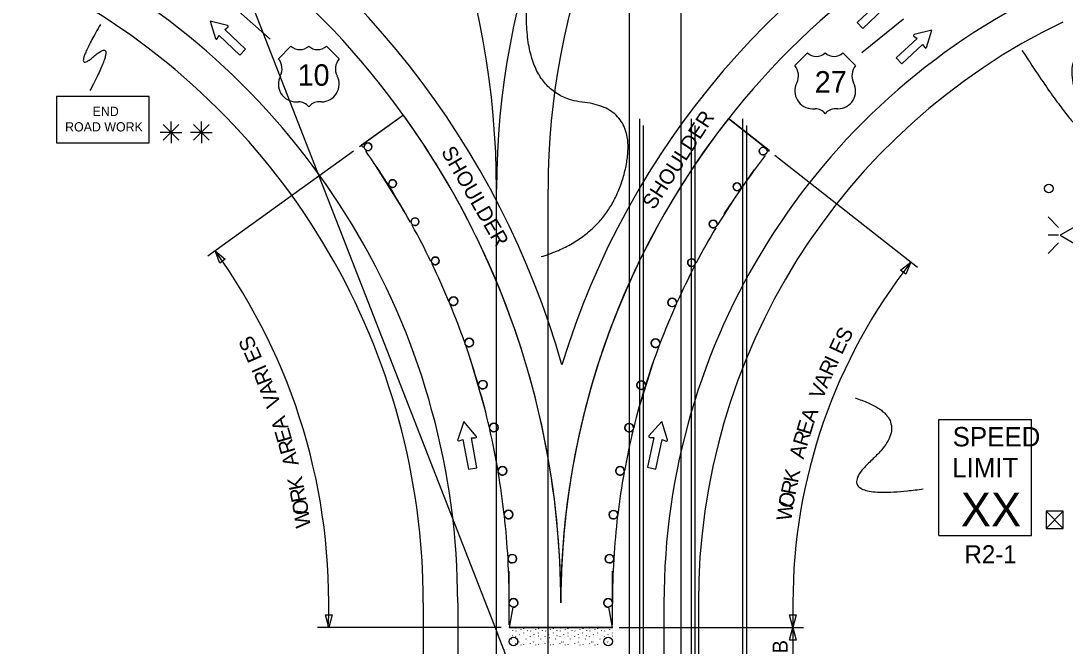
# Model space of a CAD drawing. Extents: x 16604 to 19504, y 6997 to 8305.
# Drawn here: x 16712.4 to 17198.4, y 7731.2 to 8022 of the extents above; entities that cross this region are included whole.
import ezdxf

# ---------------------------------------------------------------- set-up
doc = ezdxf.new("R2010")
doc.units = 0
for name, color, linetype in [('ALI_LEGAL_EX', 7, 'Continuous'), ('MT_SCRATCH_LEVEL_A', 7, 'Continuous'), ('MT_SCRATCH_LEVEL_E', 7, 'Continuous'), ('PAVT_EDGE_EX', 7, 'Continuous'), ('TRAFFIC_SIGNS_PR', 7, 'Continuous'), ('TYPICAL_EX', 7, 'Continuous'), ('TYPICAL_TEXT_DIMEN_PR', 7, 'Continuous')]:
    doc.layers.add(name, color=color, linetype=linetype)

msp = doc.modelspace()

# ---------------------------------------------------------------- linework, layer by layer
at = {"layer": 'ALI_LEGAL_EX'}
for p, q in [((16712.44, 8305.01), (16934.47, 7736.64)), ((16995.53, 8241.3), (16995.53, 7423.16)), ((17019.53, 8241.3), (17019.53, 7423.16)), ((17000.51, 7366.28), (17000.51, 7976.48)), ((17024.51, 7366.28), (17024.51, 7976.48)), ((17048.51, 7366.28), (17048.51, 7976.48)), ((17002.26, 7363.06), (17002.26, 7973.25)), ((17026.26, 7363.06), (17026.26, 7973.25)), ((17050.26, 7363.06), (17050.26, 7973.25)), ((16933.79, 7333.59), (16933.79, 7943.78)), ((16933.79, 7333.59), (16933.79, 7943.78)), ((16957.79, 7333.59), (16957.79, 7943.78))]:
    msp.add_line(p, q, dxfattribs=at)
for points in [[(16828.4, 8013.47), (16809.73, 8030.1)], [(17103.8, 8007.23), (17123.26, 8022.93)], [(16890.91, 7933.35), (16877.68, 7954.57)], [(17039.8, 7932.22), (17053.92, 7952.85)], [(16928.64, 7840.65), (16921.64, 7864.65)], [(16999.66, 7840.57), (17007.11, 7864.44)], [(16939.73, 7741.09), (16939.73, 7766.09)], [(16987.73, 7741.09), (16987.73, 7766.09)]]:
    msp.add_lwpolyline(points, dxfattribs=at)
for centre, radius, start, end in [((16545.79, 7943.78), 388, 0, 40.1908), ((17297.79, 7943.78), 364, 137.516, 180), ((17297.79, 7943.78), 340, 137.516, 180), ((16595.41, 7604.2), 364, 341.1459, 21.3367)]:
    msp.add_arc(centre, radius, start, end, dxfattribs=at)
at = {"layer": 'MT_SCRATCH_LEVEL_A'}
for p, q in [((16987.73, 7739.84), (16939.73, 7739.84)), ((16939.73, 7739.84), (16987.73, 7739.84)), ((16987.73, 7739.84), (16939.73, 7739.84)), ((16941.23, 7738.38), (16941.28, 7738.3)), ((16942.68, 7739.5), (16942.73, 7739.62)), ((16942.76, 7738.24), (16942.81, 7738.16)), ((16945.05, 7739.05), (16945.1, 7738.98)), ((16946.32, 7737.32), (16946.38, 7737.24)), ((16946.49, 7739.2), (16946.55, 7739.32)), ((16948.11, 7738.38), (16948.17, 7738.3)), ((16949.56, 7739.5), (16949.62, 7739.62)), ((16949.64, 7738.24), (16949.69, 7738.16)), ((16951.93, 7739.05), (16951.99, 7738.98)), ((16953.21, 7737.32), (16953.26, 7737.24)), ((16953.38, 7739.2), (16953.43, 7739.32)), ((16955, 7738.38), (16955.05, 7738.3)), ((16956.45, 7739.5), (16956.5, 7739.62)), ((16956.53, 7738.24), (16956.58, 7738.16)), ((16958.82, 7739.05), (16958.87, 7738.98)), ((16960.1, 7737.32), (16960.15, 7737.24)), ((16960.27, 7739.2), (16960.32, 7739.32)), ((16961.89, 7738.38), (16961.94, 7738.3)), ((16963.34, 7739.5), (16963.39, 7739.62)), ((16963.42, 7738.24), (16963.47, 7738.16)), ((16965.71, 7739.05), (16965.76, 7738.98)), ((16966.99, 7737.32), (16967.04, 7737.24)), ((16967.16, 7739.2), (16967.21, 7739.32)), ((16968.78, 7738.38), (16968.83, 7738.3)), ((16970.23, 7739.5), (16970.28, 7739.62)), ((16970.31, 7738.24), (16970.36, 7738.16)), ((16972.6, 7739.05), (16972.65, 7738.98)), ((16973.87, 7737.32), (16973.92, 7737.24)), ((16974.05, 7739.2), (16974.1, 7739.32)), ((16975.66, 7738.38), (16975.72, 7738.3)), ((16977.11, 7739.5), (16977.17, 7739.62)), ((16977.19, 7738.24), (16977.24, 7738.16)), ((16979.48, 7739.05), (16979.53, 7738.98)), ((16980.76, 7737.32), (16980.81, 7737.24)), ((16980.93, 7739.2), (16980.98, 7739.32)), ((16982.55, 7738.38), (16982.6, 7738.3)), ((16984, 7739.5), (16984.05, 7739.62)), ((16984.08, 7738.24), (16984.13, 7738.16)), ((16986.37, 7739.05), (16986.42, 7738.98)), ((16987.65, 7737.32), (16987.7, 7737.24)), ((16940.66, 7734.41), (16940.71, 7734.53)), ((16941.28, 7736.17), (16941.33, 7736.09)), ((16942.56, 7735.59), (16942.57, 7735.47)), ((16942.68, 7732.22), (16942.73, 7732.33)), ((16943.44, 7733.18), (16943.49, 7733.1)), ((16944.18, 7733.15), (16944.23, 7733.07)), ((16944.4, 7736.45), (16944.45, 7736.56)), ((16944.59, 7735.25), (16944.64, 7735.17)), ((16946.37, 7735.92), (16946.42, 7736.03)), ((16946.49, 7731.92), (16946.55, 7732.04)), ((16947.54, 7734.41), (16947.6, 7734.53)), ((16948.16, 7736.17), (16948.21, 7736.09)), ((16949.44, 7735.59), (16949.46, 7735.47)), ((16949.56, 7732.22), (16949.62, 7732.33)), ((16950.33, 7733.18), (16950.38, 7733.1)), ((16951.06, 7733.15), (16951.12, 7733.07)), ((16951.28, 7736.45), (16951.34, 7736.56)), ((16951.47, 7735.25), (16951.53, 7735.17)), ((16953.25, 7735.92), (16953.31, 7736.03)), ((16953.38, 7731.92), (16953.43, 7732.04)), ((16954.43, 7734.41), (16954.48, 7734.53)), ((16955.05, 7736.17), (16955.1, 7736.09)), ((16956.33, 7735.59), (16956.34, 7735.47)), ((16956.45, 7732.22), (16956.5, 7732.33)), ((16957.22, 7733.18), (16957.27, 7733.1)), ((16957.95, 7733.15), (16958, 7733.07)), ((16958.17, 7736.45), (16958.22, 7736.56)), ((16958.36, 7735.25), (16958.41, 7735.17)), ((16960.14, 7735.92), (16960.19, 7736.03)), ((16960.27, 7731.92), (16960.32, 7732.04)), ((16961.32, 7734.41), (16961.37, 7734.53)), ((16961.94, 7736.17), (16961.99, 7736.09)), ((16963.22, 7735.59), (16963.23, 7735.47)), ((16963.34, 7732.22), (16963.39, 7732.33)), ((16964.1, 7733.18), (16964.15, 7733.1)), ((16964.84, 7733.15), (16964.89, 7733.07)), ((16965.06, 7736.45), (16965.11, 7736.56)), ((16965.25, 7735.25), (16965.3, 7735.17)), ((16967.03, 7735.92), (16967.08, 7736.03)), ((16967.16, 7731.92), (16967.21, 7732.04)), ((16968.21, 7734.41), (16968.26, 7734.53)), ((16968.83, 7736.17), (16968.88, 7736.09)), ((16970.11, 7735.59), (16970.12, 7735.47)), ((16970.23, 7732.22), (16970.28, 7732.33)), ((16970.99, 7733.18), (16971.04, 7733.1)), ((16971.73, 7733.15), (16971.78, 7733.07)), ((16971.95, 7736.45), (16972, 7736.56)), ((16972.14, 7735.25), (16972.19, 7735.17)), ((16973.92, 7735.92), (16973.97, 7736.03)), ((16974.05, 7731.92), (16974.1, 7732.04)), ((16975.09, 7734.41), (16975.15, 7734.53)), ((16975.71, 7736.17), (16975.76, 7736.09)), ((16976.99, 7735.59), (16977.01, 7735.47)), ((16977.11, 7732.22), (16977.17, 7732.33)), ((16977.88, 7733.18), (16977.93, 7733.1)), ((16978.62, 7733.15), (16978.67, 7733.07)), ((16978.83, 7736.45), (16978.89, 7736.56)), ((16979.02, 7735.25), (16979.08, 7735.17)), ((16980.8, 7735.92), (16980.85, 7736.03)), ((16980.93, 7731.92), (16980.98, 7732.04)), ((16981.98, 7734.41), (16982.03, 7734.53)), ((16982.6, 7736.17), (16982.65, 7736.09)), ((16983.88, 7735.59), (16983.89, 7735.47)), ((16984, 7732.22), (16984.05, 7732.33)), ((16984.76, 7733.18), (16984.82, 7733.1)), ((16985.5, 7733.15), (16985.55, 7733.07)), ((16985.72, 7736.45), (16985.78, 7736.56)), ((16985.91, 7735.25), (16985.96, 7735.17)), ((16987.69, 7735.92), (16987.73, 7736)), ((16945.05, 7731.77), (16945.1, 7731.69)), ((16951.93, 7731.77), (16951.99, 7731.69)), ((16958.82, 7731.77), (16958.87, 7731.69)), ((16965.71, 7731.77), (16965.76, 7731.69)), ((16972.6, 7731.77), (16972.65, 7731.69)), ((16979.48, 7731.77), (16979.53, 7731.69)), ((16986.37, 7731.77), (16986.42, 7731.69))]:
    msp.add_line(p, q, dxfattribs=at)
for centre, radius, start, end in [((17327.73, 7751.28), 364, 155.5409, 180), ((17327.73, 7751.28), 364, 155.5409, 180), ((16575.73, 7751.28), 388, 0, 22.8554), ((16575.73, 7751.28), 388, 0, 22.8554)]:
    msp.add_arc(centre, radius, start, end, dxfattribs=at)
at = {"layer": 'MT_SCRATCH_LEVEL_E'}
for p, q in [((17111.32, 8030.27), (17101.65, 8021.2)), ((17104.21, 8018.47), (17113.88, 8027.53)), ((16808.64, 8019.82), (16800.53, 8021.79)), ((16800.53, 8021.79), (16802.96, 8013.82)), ((16807.35, 8017.93), (16808.8, 8019)), ((17101.65, 8021.2), (17104.21, 8018.47)), ((16803.79, 8013.7), (16804.78, 8015.21)), ((16804.78, 8015.21), (16814.4, 8006.1)), ((16816.98, 8008.81), (16807.35, 8017.93)), ((17129.52, 8013.8), (17119.85, 8004.73)), ((17128.08, 8014.88), (17129.52, 8013.8)), ((17136.34, 8017.65), (17128.24, 8015.7)), ((17133.89, 8009.67), (17136.34, 8017.65)), ((17122.41, 8002), (17132.08, 8011.07)), ((17132.08, 8011.07), (17133.06, 8009.55)), ((16814.4, 8006.1), (16816.98, 8008.81)), ((17119.85, 8004.73), (17122.41, 8002))]:
    msp.add_line(p, q, dxfattribs=at)
for centre, start, end in [((16808.52, 8019.37), 306.594, 76.331), ((16803.4, 8013.97), 196.9827, 326.5217), ((17128.36, 8015.24), 103.5821, 233.121), ((17133.45, 8009.82), 213.1934, 342.9303)]:
    msp.add_arc(centre, 0.463, start, end, dxfattribs=at)
at = {"layer": 'PAVT_EDGE_EX'}
for p, q in [((16899.73, 7751.28), (16899.73, 7396.71)), ((16915.73, 7751.28), (16915.73, 7396.71)), ((17011.73, 7751.28), (17011.73, 7396.71)), ((17027.73, 7751.28), (17027.73, 7396.71))]:
    msp.add_line(p, q, dxfattribs=at)
for centre, radius, start, end in [((16575.73, 7751.28), 404, 15.917, 60.4732), ((17327.73, 7751.28), 380, 115.7657, 163.0483), ((16575.73, 7751.28), 388, 0, 60.4732), ((17327.73, 7751.28), 364, 115.7657, 180), ((16575.73, 7751.28), 340, 0, 60.4732), ((17327.73, 7751.28), 316, 115.7657, 180), ((16575.73, 7751.28), 324, 0, 60.4732), ((17327.73, 7751.28), 300, 115.7657, 180), ((17327.73, 7751.28), 300, 180, 180.00000277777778)]:
    msp.add_arc(centre, radius, start, end, dxfattribs=at)
at = {"layer": 'TRAFFIC_SIGNS_PR'}
for p, q in [((17190.48, 7930.78), (17195.41, 7925.84)), ((17195.41, 7922.29), (17190.48, 7922.29)), ((17190.48, 7913.8), (17195.41, 7918.73)), ((17139.59, 7836.6), (17182.79, 7836.6)), ((17139.59, 7782.6), (17139.59, 7836.6)), ((17182.79, 7782.6), (17182.79, 7836.6)), ((17139.59, 7782.6), (17182.79, 7782.6))]:
    msp.add_line(p, q, dxfattribs=at)
msp.add_lwpolyline([(16728.96, 7965.21), (16772.16, 7965.21), (16772.16, 7986.81), (16728.96, 7986.81)], close=True, dxfattribs=at)
msp.add_lwpolyline([(17205.49, 7927.56), (17196.19, 7922.29), (17205.49, 7916.97)], dxfattribs=at)
for centre, radius in [((16873.98, 7963.42), 1.8), ((17057.89, 7961.41), 1.8), ((16885.43, 7946.33), 1.8), ((17045.75, 7944.81), 1.8), ((17190.82, 7943.97), 2), ((16895.89, 7928.63), 1.8), ((17034.63, 7927.51), 1.8), ((16905.35, 7910.36), 1.8), ((17024.57, 7909.57), 1.8), ((16913.77, 7891.6), 2), ((17015.59, 7891.06), 2), ((16921.12, 7872.38), 2), ((17007.76, 7872.05), 2), ((16927.38, 7852.79), 2), ((17001.08, 7852.59), 2), ((16932.52, 7832.88), 2), ((16995.58, 7832.78), 2), ((16936.54, 7812.7), 2), ((16991.28, 7812.66), 2), ((16939.42, 7792.34), 2), ((16988.2, 7792.33), 2), ((16941.15, 7771.84), 2), ((16986.34, 7771.84), 2), ((16941.73, 7751.28), 2), ((16985.72, 7751.28), 2), ((16941.73, 7733.28), 2), ((16985.72, 7733.28), 2)]:
    msp.add_circle(centre, radius, dxfattribs=at)
at = {"layer": 'TYPICAL_EX'}
for p, q in [((16832.26, 8004.38), (16838.15, 8010.27)), ((16860.56, 8004.38), (16854.66, 8010.27)), ((17072.63, 8001.2), (17078.53, 8007.09)), ((17100.93, 8001.2), (17095.03, 8007.09)), ((16840.51, 7984.32), (16841.68, 7984.32)), ((16852.31, 7984.32), (16851.13, 7984.32)), ((17080.88, 7981.14), (17082.05, 7981.14)), ((17092.68, 7981.14), (17091.5, 7981.14))]:
    msp.add_line(p, q, dxfattribs=at)
for centre, radius, start, end in [((16842.28, 8014.57), 5.96, 226.1404, 313.8596), ((16850.54, 8014.57), 5.96, 226.1404, 313.8596), ((16826.67, 7999.66), 7.31, 333.0977, 40.1936), ((16866.14, 7999.66), 7.31, 139.8064, 206.9023), ((17082.65, 8011.38), 5.96, 226.1404, 313.8596), ((17090.91, 8011.38), 5.96, 226.1404, 313.8596), ((17067.04, 7996.47), 7.31, 333.0977, 40.1936), ((17106.51, 7996.47), 7.31, 139.8064, 206.9023), ((16840.52, 7992.56), 8.24, 152.6698, 269.9013), ((16852.3, 7992.56), 8.24, 270.0987, 27.3302), ((17080.89, 7989.38), 8.24, 152.6698, 269.9013), ((17092.67, 7989.38), 8.24, 270.0987, 27.3302), ((16841.7, 7978.41), 5.91, 37.1038, 90.1385), ((16851.12, 7978.41), 5.91, 89.8615, 142.8962), ((17082.07, 7975.23), 5.91, 37.1038, 90.1385), ((17091.49, 7975.23), 5.91, 89.8615, 142.8962)]:
    msp.add_arc(centre, radius, start, end, dxfattribs=at)
at = {"layer": 'TYPICAL_TEXT_DIMEN_PR'}
for p, q in [((16782.31, 7970.13), (16782.31, 7975.14)), ((16796.43, 7970.13), (16796.43, 7975.14)), ((16890.47, 7978.18), (16870.06, 7963.46)), ((17041.83, 7976.58), (17060.9, 7961.56)), ((16782.31, 7970.13), (16777.21, 7970.13)), ((16778.72, 7973.72), (16785.89, 7966.54)), ((16785.89, 7973.72), (16778.72, 7966.54)), ((16782.31, 7970.13), (16785.89, 7970.13)), ((16782.31, 7970.13), (16787.35, 7970.13)), ((16782.31, 7970.13), (16782.31, 7965.07)), ((16796.43, 7970.13), (16791.33, 7970.13)), ((16792.85, 7973.72), (16800.02, 7966.54)), ((16800.02, 7973.72), (16792.85, 7966.54)), ((16796.43, 7970.13), (16800.02, 7970.13)), ((16796.43, 7970.13), (16801.47, 7970.13)), ((16796.43, 7970.13), (16796.43, 7965.07)), ((16867.22, 7961.41), (16799.43, 7912.54)), ((17063.39, 7959.59), (17129.66, 7907.37)), ((16805, 7909.34), (16802.85, 7915.01)), ((16802.85, 7915.01), (16807.55, 7911.17)), ((16806.28, 7910.25), (16805, 7909.34)), ((16807.55, 7911.17), (16806.28, 7910.25)), ((17121.8, 7906.1), (17126.66, 7909.74)), ((17126.66, 7909.74), (17124.27, 7904.16)), ((17123.03, 7905.13), (17121.8, 7906.1)), ((17124.27, 7904.16), (17123.03, 7905.13)), ((16918.62, 7835.66), (16915.73, 7827.27)), ((16924.39, 7828.88), (16918.62, 7835.66)), ((17010.69, 7835.66), (17004.75, 7829.06)), ((17013.35, 7827.17), (17010.69, 7835.66)), ((16916.37, 7826.64), (16918.17, 7827.32)), ((16918.17, 7827.32), (16920.77, 7813.42)), ((16922.09, 7828.06), (16924.02, 7828.07)), ((16924.69, 7814.15), (16922.09, 7828.06)), ((17007.02, 7828.16), (17003.99, 7814.35)), ((17005.09, 7828.24), (17007.02, 7828.16)), ((17007.89, 7813.49), (17010.92, 7827.3)), ((17010.92, 7827.3), (17012.7, 7826.57)), ((16920.77, 7813.42), (16924.69, 7814.15)), ((17003.99, 7814.35), (17007.89, 7813.49)), ((17189.58, 7793.92), (17197.58, 7785.92)), ((17189.58, 7785.92), (17197.58, 7793.92)), ((17071.73, 7751.28), (17071.73, 7739.84)), ((16855.73, 7739.84), (16854.16, 7745.7)), ((16854.16, 7745.7), (16855.73, 7745.7)), ((16855.73, 7745.7), (16857.3, 7745.7)), ((16857.3, 7745.7), (16855.73, 7739.84)), ((17071.73, 7739.84), (17070.16, 7745.7)), ((17070.16, 7745.7), (17071.73, 7745.7)), ((17071.73, 7745.7), (17073.3, 7745.7)), ((17073.3, 7745.7), (17071.73, 7739.84)), ((16936.02, 7739.84), (16850.49, 7739.84)), ((16990.92, 7739.84), (17076.73, 7739.84)), ((17070.16, 7733.97), (17071.73, 7739.84)), ((17071.73, 7739.84), (17071.73, 7717.28)), ((17071.73, 7739.84), (17073.3, 7733.97)), ((17071.73, 7733.97), (17070.16, 7733.97)), ((17073.3, 7733.97), (17071.73, 7733.97))]:
    msp.add_line(p, q, dxfattribs=at)
for points in [[(16890.47, 7978.18), (16871, 7964.14)], [(17060.69, 7961.73), (17041.83, 7976.58)], [(16871.5, 7963.45), (16872.18, 7963.45)], [(16873.38, 7961.72), (16872.95, 7961.42)], [(17059.69, 7961.52), (17060.54, 7961.54)], [(17058.8, 7959.31), (17058.35, 7959.67)], [(16883.22, 7946.07), (16883.63, 7946.33)], [(16884.64, 7944.71), (16884.24, 7944.46)], [(17046.83, 7942.84), (17046.41, 7943.13)], [(17047.55, 7944.81), (17047.98, 7944.51)], [(16893.72, 7928.42), (16894.09, 7928.62)], [(16894.93, 7927.1), (16894.56, 7926.9)], [(17036.43, 7927.51), (17036.82, 7927.27)], [(17035.87, 7925.69), (17035.48, 7925.92)], [(16903.21, 7910.2), (16903.55, 7910.36)], [(16904.22, 7908.96), (16903.89, 7908.79)], [(17025.96, 7907.91), (17025.6, 7908.1)], [(17026.37, 7909.57), (17026.72, 7909.38)], [(16911.62, 7891.53), (16911.77, 7891.6)], [(16912.35, 7890.19), (16912.21, 7890.13)], [(17017.09, 7889.51), (17016.93, 7889.58)], [(17017.6, 7891.06), (17017.76, 7890.99)], [(16919.01, 7872.35), (16919.12, 7872.38)], [(16919.55, 7871.14), (16919.44, 7871.1)], [(17009.39, 7870.69), (17009.26, 7870.73)], [(17009.76, 7872.05), (17009.88, 7872)], [(16925.3, 7852.77), (16925.38, 7852.79)], [(16925.68, 7851.73), (16925.6, 7851.71)], [(17002.82, 7851.44), (17002.73, 7851.47)], [(17003.08, 7852.6), (17003.17, 7852.57)], [(16930.47, 7832.86), (16930.52, 7832.88)], [(16930.72, 7832.01), (16930.67, 7832)], [(16997.41, 7831.84), (16997.35, 7831.86)], [(16997.58, 7832.78), (16997.64, 7832.76)], [(16934.51, 7812.7), (16934.54, 7812.7)], [(16934.65, 7812.05), (16934.62, 7812.04)], [(16993.19, 7811.95), (16993.15, 7811.96)], [(16993.28, 7812.66), (16993.31, 7812.65)], [(16937.41, 7792.34), (16937.42, 7792.34)], [(16937.47, 7791.9), (16937.46, 7791.89)], [(16990.16, 7791.85), (16990.14, 7791.85)], [(16990.2, 7792.32), (16990.22, 7792.32)], [(16939.15, 7771.84), (16939.15, 7771.84)], [(16939.17, 7771.62), (16939.16, 7771.62)], [(16988.34, 7771.6), (16988.33, 7771.6)], [(16988.34, 7771.84), (16988.35, 7771.84)], [(16939.73, 7751.28), (16939.74, 7751.28)], [(16941.39, 7749.31), (16939.73, 7739.84), (16987.73, 7739.84), (16986.07, 7749.31)], [(16987.72, 7751.28), (16987.73, 7751.28)]]:
    msp.add_lwpolyline(points, dxfattribs=at)
msp.add_lwpolyline([(17189.58, 7793.92), (17189.58, 7785.92), (17197.58, 7785.92), (17197.58, 7793.92)], close=True, dxfattribs=at)
for centre, radius, start, end in [((16575.73, 7751.28), 388, 22.8554, 35.7873), ((17327.73, 7751.28), 364, 141.7598, 180), ((16873.98, 7963.42), 1.8, 0, 179.0978), ((16575.73, 7751.28), 364, 35.6537, 35.7873), ((16575.73, 7751.28), 364, 32.3536, 35.2603), ((16873.98, 7963.42), 1.8, 250.5205, 0), ((17057.89, 7961.41), 1.8, 3.5129, 180), ((17057.89, 7961.41), 1.8, 180, 284.5518), ((17327.73, 7751.28), 340, 141.7598, 141.7992), ((17327.73, 7751.28), 340, 142.2759, 145.3661), ((16885.43, 7946.33), 1.8, 0, 180), ((16885.43, 7946.33), 1.8, 244.1065, 0), ((17045.75, 7944.81), 1.8, 0, 180), ((16575.73, 7751.28), 364, 29.1198, 32.0533), ((17327.73, 7751.28), 340, 145.7074, 148.8275), ((17045.75, 7944.81), 1.8, 180, 291.4148), ((16895.89, 7928.63), 1.8, 0, 180), ((16575.73, 7751.28), 364, 25.8855, 28.8467), ((16895.89, 7928.63), 1.8, 237.6934, 0), ((17034.63, 7927.51), 1.8, 0, 180), ((17034.63, 7927.51), 1.8, 180, 298.2766), ((17327.73, 7751.28), 340, 149.1383, 152.2895), ((16575.89, 7751.27), 279.86, 357.6585, 35.8088), ((16905.35, 7910.36), 1.8, 0, 180), ((16575.73, 7751.28), 364, 22.663, 25.6406), ((16905.35, 7910.36), 1.8, 231.2811, 0), ((17327.73, 7751.28), 340, 152.5687, 155.7382), ((17024.57, 7909.57), 1.8, 0, 180), ((17024.57, 7909.57), 1.8, 180, 305.1374), ((17327.73, 7751.28), 256, 141.7598, 180), ((16575.73, 7751.28), 388, 0, 22.8554), ((16913.77, 7891.6), 2, 0, 180), ((17015.59, 7891.06), 2, 0, 180), ((16575.73, 7751.28), 364, 19.4261, 22.4229), ((16913.77, 7891.6), 2, 224.8459, 0), ((17327.73, 7751.28), 340, 156.0121, 159.2032), ((17015.59, 7891.06), 2, 180, 312.0242), ((16921.12, 7872.38), 2, 0, 180), ((17007.76, 7872.05), 2, 0, 180), ((16575.73, 7751.28), 364, 16.189, 19.219), ((16921.12, 7872.38), 2, 218.4379, 0), ((17327.73, 7751.28), 340, 159.4399, 162.6687), ((17007.76, 7872.05), 2, 180, 318.8797), ((16927.38, 7852.79), 2, 0, 180), ((17001.08, 7852.59), 2, 0, 180), ((16575.73, 7751.28), 364, 12.9515, 16.0153), ((16927.38, 7852.79), 2, 212.0306, 0), ((17327.73, 7751.28), 340, 162.8672, 166.1345), ((17001.08, 7852.59), 2, 180, 325.7344), ((16932.52, 7832.88), 2, 0, 180), ((16995.58, 7832.78), 2, 0, 180), ((16575.73, 7751.28), 364, 9.7138, 12.8119), ((16932.52, 7832.88), 2, 205.6238, 0), ((17327.73, 7751.28), 340, 166.2942, 169.6006), ((16995.58, 7832.78), 2, 180, 332.5884), ((16916.2, 7827.11), 0.494, 161.0027, 290.5416), ((16924, 7828.57), 0.494, 270.614, 40.3509), ((17005.12, 7828.73), 0.494, 138.0497, 267.5887), ((17012.87, 7827.03), 0.494, 247.6611, 17.398), ((16936.54, 7812.7), 2, 0, 180), ((16991.28, 7812.66), 2, 0, 180), ((16575.73, 7751.28), 364, 6.476, 9.6087), ((16936.54, 7812.7), 2, 199.2175, 0), ((16991.28, 7812.66), 2, 180, 339.4418), ((17327.73, 7751.28), 340, 169.7209, 173.067), ((16939.42, 7792.34), 2, 0, 180), ((16575.73, 7751.28), 364, 3.238, 6.4057), ((16939.42, 7792.34), 2, 192.8115, 0), ((16988.2, 7792.33), 2, 0, 180), ((16988.2, 7792.33), 2, 180, 346.2947), ((17327.73, 7751.28), 340, 173.1474, 176.5334), ((16941.15, 7771.84), 2, 0, 180), ((16575.73, 7751.28), 364, 0, 3.2028), ((16941.15, 7771.84), 2, 186.4057, 0), ((16986.34, 7771.84), 2, 0, 180), ((16986.34, 7771.84), 2, 180, 353.1474), ((17327.73, 7751.28), 340, 176.5737, 180), ((16941.73, 7751.28), 2, 0, 180), ((16985.72, 7751.28), 2, 0, 180), ((16941.73, 7751.28), 2, 260.0595, 0), ((16985.72, 7751.28), 2, 180, 279.941)]:
    msp.add_arc(centre, radius, start, end, dxfattribs=at)
for points in [[(16954.55, 7912.33), (16985.92, 7921.76), (17000.86, 7981.24), (16947.66, 7986.96), (16947.76, 8062.72), (16997.69, 8066.32)], [(16749.51, 8020.34), (16735.05, 7995.71), (16758.27, 8015.56), (16744.61, 7989.55)], [(17178.35, 8008.18), (17216.58, 7950.01), (17193.37, 8015.71), (17222.72, 8006.13)], [(17100.69, 7846.59), (17130.21, 7837.43), (17086.62, 7797.96), (17132.32, 7804.3)]]:
    msp.add_open_spline(points, degree=2, dxfattribs=at)

# ---------------------------------------------------------------- texts
at = {"layer": 'TRAFFIC_SIGNS_PR'}
for s, height, p in [('END', 4.31, (16745.83, 7977.73)), ('ROAD WORK', 4.31, (16733.02, 7970.55)), ('SPEED', 9, (17146.08, 7824.07)), ('LIMIT', 9, (17145.9, 7809.67)), ('XX', 15.785, (17149.84, 7786.83)), ('R2-1', 8.37, (17151.6, 7769.73))]:
    msp.add_text(s, height=height, dxfattribs=at).set_placement(p)
at = {"layer": 'TYPICAL_EX'}
for s, p in [('10', (16841.25, 7991.8)), ('27', (17081.89, 7988.62))]:
    msp.add_text(s, height=10, dxfattribs=at).set_placement(p)
at = {"layer": 'TYPICAL_TEXT_DIMEN_PR'}
for s, rotation, p in [('SHOULDER', 56.8597, (17007.03, 7933.74)), ('SHOULDER', 300.0663, (16907.81, 7961.18)), ('S', 62.4974, (17097.26, 7871.66)), ('S', 116.1586, (16822.42, 7870.58)), ('E', 65.1772, (17094.57, 7866.37)), ('E', 113.6993, (16824.91, 7865.07)), ('R', 65.1772, (17089.9, 7856.29)), ('I', 65.1772, (17092.41, 7861.71)), ('I', 113.6993, (16826.97, 7860.38)), ('R', 111.1369, (16829.42, 7854.45)), ('A', 111.1369, (16831.48, 7849.12)), ('V', 67.857, (17085.53, 7845.53)), ('A', 67.857, (17087.63, 7850.69)), ('V', 108.5745, (16833.57, 7843.49)), ('A', 70.5368, (17081.65, 7834.65)), ('A', 108.5745, (16837.15, 7832.84)), ('E', 73.2167, (17079.9, 7829.07)), ('E', 106.0121, (16838.79, 7827.11)), ('R', 73.2167, (17078.27, 7823.67)), ('R', 106.0121, (16840.34, 7821.69)), ('A', 103.4497, (16841.83, 7815.71)), ('A', 75.8965, (17076.7, 7817.83)), ('K', 100.8873, (16844.37, 7804.44)), ('K', 78.5763, (17074.05, 7806.71)), ('R', 100.8873, (16845.45, 7798.79)), ('R', 78.5763, (17072.91, 7801.07)), ('O', 81.2562, (17071.83, 7795.11)), ('O', 98.3249, (16846.51, 7792.71)), ('W', 81.2562, (17070.9, 7789.08)), ('W', 98.3249, (16847.39, 7786.68)), ('B', 90, (17069.29, 7727.79))]:
    msp.add_text(s, height=7, rotation=rotation, dxfattribs=at).set_placement(p)

doc.saveas('drawing.dxf')
